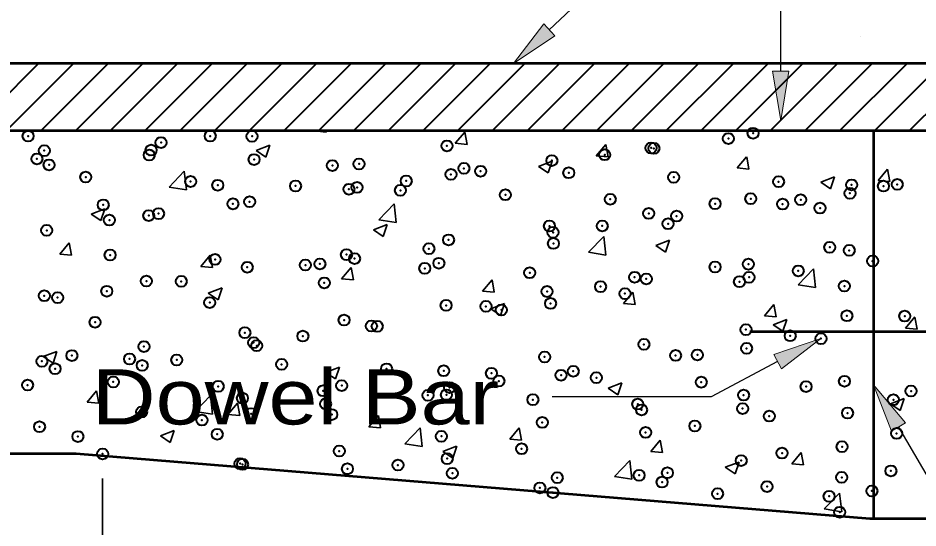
# Model space of a CAD drawing. Extents: x 36.4 to 71.7, y 0.5 to 22.5.
# Drawn here: x 55.644 to 57.934, y 8.925 to 10.222 of the extents above; entities that cross this region are included whole.
import ezdxf

# ---------------------------------------------------------------- set-up
doc = ezdxf.new("R2010")
doc.units = 0
doc.header["$LTSCALE"] = 0.056
doc.header["$PDMODE"] = 32
doc.header["$PDSIZE"] = 0.028
for name, color, linetype, lineweight in [('1', 7, 'Continuous', 40), ('3', 7, 'Continuous', 13), ('6', 7, 'Continuous', 13)]:
    doc.layers.add(name, color=color, linetype=linetype, lineweight=lineweight)

msp = doc.modelspace()

# ---------------------------------------------------------------- hatches: boundary and pattern name
at = {"layer": '3'}
for points in [[(57.01, 10.17667), (56.98142, 10.20692), (56.90458, 10.10608), (56.90458, 10.10608)], [(57.6055, 10.08658), (57.56383, 10.08658), (57.58458, 9.96158), (57.58458, 9.96158)], [(57.56675, 9.3665), (57.58625, 9.32975), (57.68692, 9.40658), (57.68692, 9.40658)], [(57.86617, 9.17108), (57.90217, 9.19217), (57.821, 9.28942), (57.821, 9.28942)]]:
    msp.add_hatch(color=256, dxfattribs=at).paths.add_polyline_path(points)

# ---------------------------------------------------------------- linework, layer by layer
at = {"layer": '1', "lineweight": 53}
for p, q in [((58.57958, 10.10608), (53.98842, 10.10608)), ((57.821, 9.9355), (57.821, 8.94833)), ((58.12642, 9.42383), (57.50567, 9.42383))]:
    msp.add_line(p, q, dxfattribs=at)
at = {"layer": '1'}
for p, q in [((55.52558, 9.9355), (55.69625, 10.10608)), ((55.614, 9.9355), (55.78458, 10.10608)), ((55.70242, 9.9355), (55.873, 10.10608)), ((55.79075, 9.9355), (55.96133, 10.10608)), ((55.87917, 9.9355), (56.04975, 10.10608)), ((55.96758, 9.9355), (56.13817, 10.10608)), ((56.05592, 9.9355), (56.2265, 10.10608)), ((56.14433, 9.9355), (56.31492, 10.10608)), ((56.23275, 9.9355), (56.40333, 10.10608)), ((56.32108, 9.9355), (56.49167, 10.10608)), ((56.4095, 9.9355), (56.58008, 10.10608)), ((56.49792, 9.9355), (56.6685, 10.10608)), ((56.58625, 9.9355), (56.75683, 10.10608)), ((56.67467, 9.9355), (56.84525, 10.10608)), ((56.76308, 9.9355), (56.93367, 10.10608)), ((56.85142, 9.9355), (57.022, 10.10608)), ((56.93983, 9.9355), (57.11042, 10.10608)), ((57.02825, 9.9355), (57.19883, 10.10608)), ((57.11658, 9.9355), (57.28717, 10.10608)), ((57.205, 9.9355), (57.37558, 10.10608)), ((57.29342, 9.9355), (57.464, 10.10608)), ((57.38175, 9.9355), (57.55233, 10.10608)), ((57.47017, 9.9355), (57.64075, 10.10608)), ((57.55858, 9.9355), (57.72917, 10.10608)), ((57.64692, 9.9355), (57.8175, 10.10608)), ((57.73533, 9.9355), (57.90592, 10.10608)), ((57.82367, 9.9355), (57.99433, 10.10608)), ((57.91208, 9.9355), (58.08267, 10.10608))]:
    msp.add_line(p, q, dxfattribs=at)
at = {"layer": '1', "lineweight": 35}
for p, q in [((56.39783, 9.9345), (56.39867, 9.9355)), ((56.39783, 9.9345), (56.42775, 9.93192)), ((56.42775, 9.93192), (56.42708, 9.9355)), ((56.7565, 9.90317), (56.78058, 9.93183)), ((56.78642, 9.9005), (56.78058, 9.93183)), ((56.24958, 9.88467), (56.28458, 9.89808)), ((56.2745, 9.86783), (56.28467, 9.89808)), ((56.7565, 9.90317), (56.78642, 9.9005)), ((57.11517, 9.87175), (57.13925, 9.9005)), ((57.145, 9.86917), (57.13925, 9.9005)), ((56.24958, 9.88467), (56.2745, 9.86792)), ((57.11517, 9.87175), (57.145, 9.86917)), ((56.96817, 9.84458), (57.00317, 9.85808)), ((56.99308, 9.82783), (57.00317, 9.858)), ((57.47375, 9.84042), (57.49783, 9.86908)), ((57.50367, 9.83775), (57.49792, 9.86908)), ((56.028, 9.79158), (56.06692, 9.83217)), ((56.0725, 9.78467), (56.06692, 9.83217)), ((56.96817, 9.84458), (56.99308, 9.82783)), ((57.47375, 9.84042), (57.50367, 9.83775)), ((57.83242, 9.809), (57.8565, 9.83775)), ((57.86225, 9.80633), (57.8565, 9.83775)), ((57.68675, 9.80458), (57.72175, 9.818)), ((57.68675, 9.80458), (57.71158, 9.78783)), ((57.71158, 9.78775), (57.72175, 9.818)), ((57.83242, 9.809), (57.86225, 9.80642)), ((56.028, 9.79158), (56.0725, 9.78467)), ((55.8295, 9.72342), (55.8645, 9.73683)), ((55.85442, 9.70658), (55.8645, 9.73683)), ((56.56158, 9.70883), (56.60058, 9.74942)), ((56.60608, 9.70192), (56.60058, 9.74942)), ((55.8295, 9.72342), (55.85433, 9.70658)), ((56.54808, 9.68333), (56.58308, 9.69675)), ((56.56158, 9.70883), (56.60608, 9.70192)), ((56.57292, 9.66658), (56.58308, 9.69675)), ((56.54808, 9.68333), (56.57292, 9.66658)), ((57.09525, 9.62608), (57.13417, 9.66667)), ((57.13975, 9.61917), (57.13417, 9.66667)), ((55.75, 9.62117), (55.77408, 9.64992)), ((55.77992, 9.6185), (55.77408, 9.64992)), ((57.26667, 9.64333), (57.30167, 9.65675)), ((57.26667, 9.64333), (57.2915, 9.6265)), ((57.2915, 9.6265), (57.30167, 9.65675)), ((55.75, 9.62117), (55.77983, 9.61858)), ((57.09525, 9.62608), (57.13975, 9.61917)), ((56.10858, 9.58975), (56.13275, 9.6185)), ((56.1385, 9.58717), (56.13275, 9.6185)), ((56.10858, 9.58975), (56.1385, 9.58717)), ((56.46725, 9.55842), (56.49133, 9.58717)), ((56.49717, 9.55575), (56.49133, 9.58708)), ((57.62883, 9.54333), (57.66783, 9.58392)), ((57.67333, 9.53642), (57.66783, 9.58392)), ((56.46725, 9.55842), (56.49717, 9.55583)), ((56.82592, 9.527), (56.85, 9.55575)), ((56.85575, 9.52442), (56.85, 9.55575)), ((56.12792, 9.52208), (56.163, 9.5355)), ((56.15283, 9.50533), (56.163, 9.5355)), ((57.62883, 9.54333), (57.67333, 9.53642)), ((56.12792, 9.52208), (56.15283, 9.50533)), ((56.82592, 9.527), (56.85575, 9.52442)), ((57.1845, 9.49567), (57.20858, 9.52442)), ((57.21442, 9.493), (57.20858, 9.52433)), ((56.8465, 9.48208), (56.8815, 9.4955)), ((56.8465, 9.48208), (56.87142, 9.46525)), ((56.87142, 9.46525), (56.8815, 9.4955)), ((57.1845, 9.49567), (57.21442, 9.49308)), ((57.54317, 9.46425), (57.56725, 9.493)), ((57.573, 9.46167), (57.56725, 9.493)), ((57.54317, 9.46425), (57.573, 9.46167)), ((57.90175, 9.43292), (57.92583, 9.46167)), ((57.93167, 9.43025), (57.92592, 9.46158)), ((57.56508, 9.442), (57.60008, 9.45542)), ((57.56508, 9.442), (57.58992, 9.42525)), ((57.59, 9.42517), (57.60008, 9.45542)), ((57.90175, 9.43292), (57.93167, 9.43033)), ((55.70783, 9.36083), (55.74283, 9.37425)), ((55.73275, 9.344), (55.74283, 9.37425)), ((55.73275, 9.344), (55.74283, 9.37425)), ((55.70783, 9.36083), (55.73275, 9.34408)), ((56.42642, 9.32075), (56.46142, 9.33425)), ((56.45125, 9.304), (56.46142, 9.33417)), ((56.42642, 9.32075), (56.45125, 9.304)), ((57.145, 9.28075), (57.18, 9.29417)), ((57.145, 9.28075), (57.18, 9.29417)), ((57.145, 9.28075), (57.16983, 9.26392)), ((57.16983, 9.26392), (57.18, 9.29417)), ((55.81933, 9.24508), (55.8435, 9.27383)), ((55.84925, 9.24242), (55.8435, 9.27375)), ((56.09425, 9.22175), (56.13325, 9.26233)), ((56.13875, 9.21483), (56.13325, 9.26233)), ((57.8635, 9.24067), (57.89858, 9.25417)), ((57.88842, 9.22392), (57.89858, 9.25408)), ((55.81933, 9.24508), (55.84925, 9.24242)), ((56.178, 9.21367), (56.20208, 9.24242)), ((56.20792, 9.21108), (56.20208, 9.24242)), ((57.8635, 9.24067), (57.88842, 9.22392)), ((56.09425, 9.22175), (56.13875, 9.21483)), ((56.178, 9.21367), (56.20792, 9.21108)), ((56.53658, 9.18233), (56.56075, 9.21108)), ((56.5665, 9.17967), (56.56075, 9.211)), ((56.00633, 9.1595), (56.04133, 9.17292)), ((56.03117, 9.14275), (56.04133, 9.17292)), ((56.53658, 9.18233), (56.5665, 9.17967)), ((56.62792, 9.139), (56.66683, 9.17958)), ((56.67242, 9.13208), (56.66683, 9.17958)), ((56.89525, 9.15092), (56.91933, 9.17967)), ((56.92517, 9.14833), (56.91933, 9.17967)), ((56.00633, 9.1595), (56.03117, 9.14275)), ((56.62792, 9.139), (56.67242, 9.13208)), ((56.89525, 9.15092), (56.92517, 9.14833)), ((57.25392, 9.11958), (57.278, 9.14825)), ((57.28375, 9.11692), (57.278, 9.14825)), ((57.28375, 9.11692), (57.278, 9.14825)), ((56.72483, 9.1195), (56.75983, 9.13292)), ((56.72483, 9.1195), (56.74975, 9.10267)), ((56.74975, 9.10267), (56.75992, 9.13292)), ((57.25392, 9.11958), (57.28375, 9.11692)), ((57.6125, 9.08817), (57.63658, 9.11692)), ((57.64242, 9.08558), (57.63667, 9.11692)), ((57.1615, 9.05625), (57.2005, 9.09683)), ((57.206, 9.04933), (57.2005, 9.09683)), ((57.44342, 9.07942), (57.47842, 9.09283)), ((57.46833, 9.06267), (57.47842, 9.09283)), ((57.44342, 9.07942), (57.46833, 9.06267)), ((57.6125, 9.08817), (57.64242, 9.08558)), ((55.859, 9.051), (55.859, 7.96225)), ((57.1615, 9.05625), (57.206, 9.04933)), ((57.69517, 8.9735), (57.73408, 9.01408)), ((57.73967, 8.96658), (57.73408, 9.01408)), ((57.69517, 8.9735), (57.73958, 8.96658))]:
    msp.add_line(p, q, dxfattribs=at)
at = {"layer": '1', "lineweight": 53}
for points in [[(53.98842, 9.9355), (58.57958, 9.9355), (58.57958, 10.10608)], [(58.57958, 8.94833), (57.81108, 8.94833), (55.79142, 9.11375), (53.98842, 9.11375)]]:
    msp.add_lwpolyline(points, dxfattribs=at)
at = {"layer": '1'}
for p in [(57.51433, 9.92883), (55.6695, 9.92158), (56.00758, 9.90517), (56.13275, 9.92167), (56.23917, 9.92108), (57.45125, 9.91533), (55.71067, 9.8845), (55.9825, 9.88583), (56.73525, 9.89675), (57.25458, 9.89133), (57.26183, 9.89042), (55.69183, 9.86358), (55.97758, 9.87325), (56.2445, 9.862), (57.00208, 9.85933), (57.13667, 9.87392), (55.72275, 9.84833), (56.44367, 9.84675), (56.51142, 9.85067), (56.77833, 9.83942), (55.81608, 9.81733), (56.74533, 9.82408), (56.82092, 9.83233), (57.04525, 9.82817), (57.31217, 9.81683), (56.083, 9.80608), (56.15208, 9.79667), (56.34992, 9.79483), (56.50633, 9.79092), (56.6315, 9.80742), (57.57908, 9.80558), (57.76492, 9.79758), (57.846, 9.79433), (57.881, 9.79867), (56.48567, 9.78658), (56.61683, 9.7835), (56.88375, 9.77225), (57.76067, 9.77617), (55.8605, 9.74667), (56.19058, 9.74933), (56.23308, 9.75458), (57.15067, 9.761), (57.41758, 9.74967), (57.50825, 9.76233), (57.58942, 9.74858), (57.63542, 9.75967), (55.97642, 9.71942), (56.00125, 9.72442), (57.2485, 9.72483), (57.6845, 9.73842), (55.87608, 9.70792), (57.29783, 9.69858), (57.31967, 9.71808), (55.71667, 9.68192), (56.996, 9.69283), (57.00517, 9.67667), (57.13033, 9.69317), (56.73925, 9.65767), (56.68933, 9.63517), (57.00625, 9.6485), (57.70925, 9.63883), (57.75883, 9.63108), (55.87817, 9.61908), (56.145, 9.60783), (56.47958, 9.62017), (56.5, 9.61017), (56.227, 9.58817), (56.37483, 9.59375), (56.41192, 9.59658), (56.67883, 9.58525), (56.71458, 9.59842), (57.41758, 9.58875), (57.50217, 9.59592), (57.81842, 9.60392), (56.94575, 9.574), (57.21267, 9.56275), (57.50392, 9.5625), (57.62908, 9.57892), (55.97033, 9.55292), (56.05908, 9.55217), (56.423, 9.54842), (57.126, 9.53875), (57.2425, 9.55842), (57.47958, 9.55142), (57.7465, 9.54017), (55.71058, 9.5155), (55.86967, 9.52725), (56.98992, 9.52642), (57.18817, 9.52092), (55.7445, 9.51075), (56.13142, 9.49833), (56.73317, 9.49125), (56.99875, 9.496), (56.83442, 9.48867), (56.87358, 9.4795), (55.83983, 9.44833), (56.4735, 9.45375), (57.75283, 9.46467), (57.90017, 9.46383), (56.22092, 9.42175), (56.54283, 9.43858), (56.55783, 9.43792), (57.49608, 9.4295), (56.3685, 9.413), (57.60858, 9.41383), (57.68692, 9.40667), (55.96425, 9.3865), (56.24333, 9.3965), (56.25125, 9.38858), (57.23642, 9.392), (57.49758, 9.38175), (55.78075, 9.36358), (55.9275, 9.35492), (56.98383, 9.36), (57.317, 9.36375), (57.37242, 9.36525), (55.7045, 9.349), (55.73817, 9.33), (55.95967, 9.3385), (56.04767, 9.35233), (56.31458, 9.34108), (56.5815, 9.32975), (56.72708, 9.32475), (56.84842, 9.3185), (57.02542, 9.31367), (57.05658, 9.32367), (57.11533, 9.30725), (55.66808, 9.2885), (55.88617, 9.29642), (56.15308, 9.28517), (56.46742, 9.28725), (56.86725, 9.29875), (57.38225, 9.29592), (57.64917, 9.28467), (57.74675, 9.29825), (56.42, 9.27392), (56.68692, 9.26258), (56.73383, 9.26367), (56.74208, 9.28225), (57.49, 9.263), (57.91608, 9.27342), (56.21483, 9.25525), (56.42633, 9.24075), (56.95383, 9.25133), (57.22075, 9.24008), (57.87117, 9.25108), (55.95817, 9.22008), (56.23692, 9.21575), (57.23033, 9.2255), (57.48767, 9.22875), (57.75458, 9.2175), (56.11175, 9.19933), (56.44217, 9.21358), (56.97775, 9.1935), (57.55542, 9.2095), (55.69842, 9.18258), (57.366, 9.18458), (55.796, 9.15775), (56.15058, 9.1635), (56.721, 9.15833), (57.24083, 9.16808), (57.8795, 9.1655), (56.92508, 9.1265), (57.74067, 9.13175), (55.859, 9.1135), (56.46133, 9.12083), (56.73575, 9.10158), (57.58792, 9.1155), (56.20875, 9.08883), (56.21508, 9.08692), (56.6105, 9.08508), (57.48392, 9.09658), (56.482, 9.07558), (56.74892, 9.06433), (57.22425, 9.05908), (57.29633, 9.06542), (57.86483, 9.07033), (57.01583, 9.05308), (57.28275, 9.04175), (57.73967, 9.05383), (56.97167, 9.02708), (57.00475, 9.01533), (57.42383, 9.01225), (57.54967, 9.0305), (57.81658, 9.01925), (57.70775, 9.00567), (57.73458, 8.96533)]:
    msp.add_point(p, dxfattribs=at)
at = {"layer": '3', "lineweight": 25}
for points in [[(57.58467, 10.08658), (57.58467, 11.46008), (56.92442, 11.46008)], [(56.99567, 10.19183), (57.486, 10.65383), (57.2495, 10.65383)], [(57.5765, 9.34817), (57.40717, 9.25842), (57.00325, 9.25842)], [(57.88417, 9.18158), (58.98358, 7.30492), (59.19042, 7.30492)]]:
    msp.add_lwpolyline(points, dxfattribs=at)
at = {"layer": '3'}
for points in [[(57.01, 10.17667), (56.98142, 10.20692), (56.90458, 10.10608), (56.90458, 10.10608)], [(57.6055, 10.08658), (57.56383, 10.08658), (57.58458, 9.96158), (57.58458, 9.96158)], [(57.56675, 9.3665), (57.58625, 9.32975), (57.68692, 9.40658), (57.68692, 9.40658)], [(57.86617, 9.17108), (57.90217, 9.19217), (57.821, 9.28942), (57.821, 9.28942)]]:
    msp.add_lwpolyline(points, close=True, dxfattribs=at)
at = {"layer": '6'}
for p, q in [((57.78717, 10.17408), (57.78725, 10.17408)), ((57.78717, 10.17408), (57.78725, 10.17408)), ((55.859, 9.1135), (55.85908, 9.1135)), ((57.821, 8.94833), (57.82108, 8.94833))]:
    msp.add_line(p, q, dxfattribs=at)

# ---------------------------------------------------------------- texts
at = {"layer": '3', "width": 1.2}
msp.add_text('Dowel Bar', height=0.14, dxfattribs=at).set_placement((55.83158, 9.18842))

doc.saveas('drawing.dxf')
